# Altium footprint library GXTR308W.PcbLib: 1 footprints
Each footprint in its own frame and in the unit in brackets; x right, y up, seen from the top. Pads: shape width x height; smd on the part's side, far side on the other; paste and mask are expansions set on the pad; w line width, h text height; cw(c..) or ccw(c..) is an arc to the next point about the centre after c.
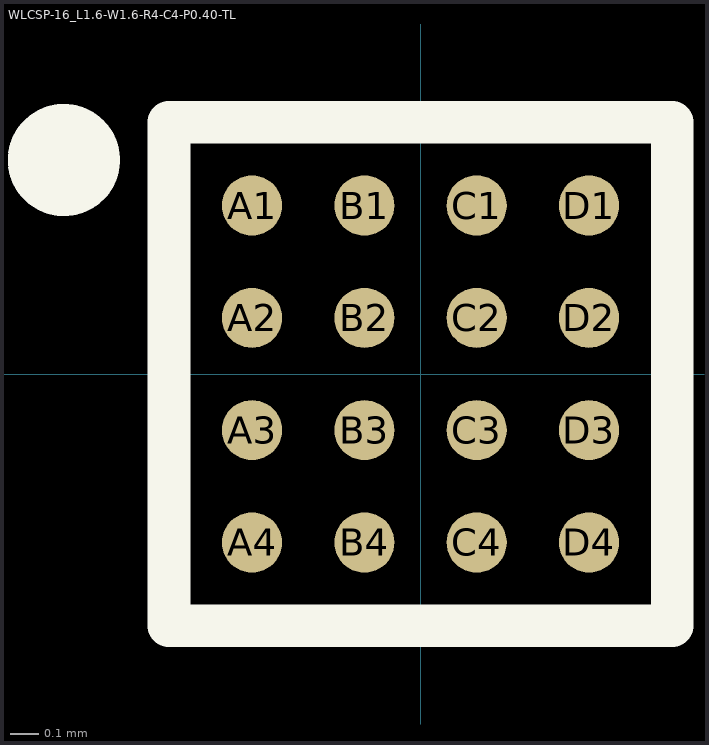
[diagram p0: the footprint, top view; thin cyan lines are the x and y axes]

## WLCSP-16_L1.6-W1.6-R4-C4-P0.40-TL [mm]
pads (16):
  round 0.214 smd paste-100 mask+0.051: A1(-0.6,0.6) A2(-0.6,0.2) A3(-0.6,-0.2) A4(-0.6,-0.6) B1(-0.2,0.6) B2(-0.2,0.2) B3(-0.2,-0.2) B4(-0.2,-0.6) C1(0.2,0.6) C2(0.2,0.2) C3(0.2,-0.2) C4(0.2,-0.6) D1(0.6,0.6) D2(0.6,0.2) D3(0.6,-0.2) D4(0.6,-0.6)
Top Overlay:
  circle w0.2: c-1.27,0.762 r0.1
  lines w0.152: -0.896,-0.896 0.896,-0.896 0.896,0.896 -0.896,0.896 -0.896,-0.896
3D body "WLCSP-16-1.60X1.60-P0.4.STEP": height 0.58, standoff 0, extent -0.827,-0.82 0.813,0.82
